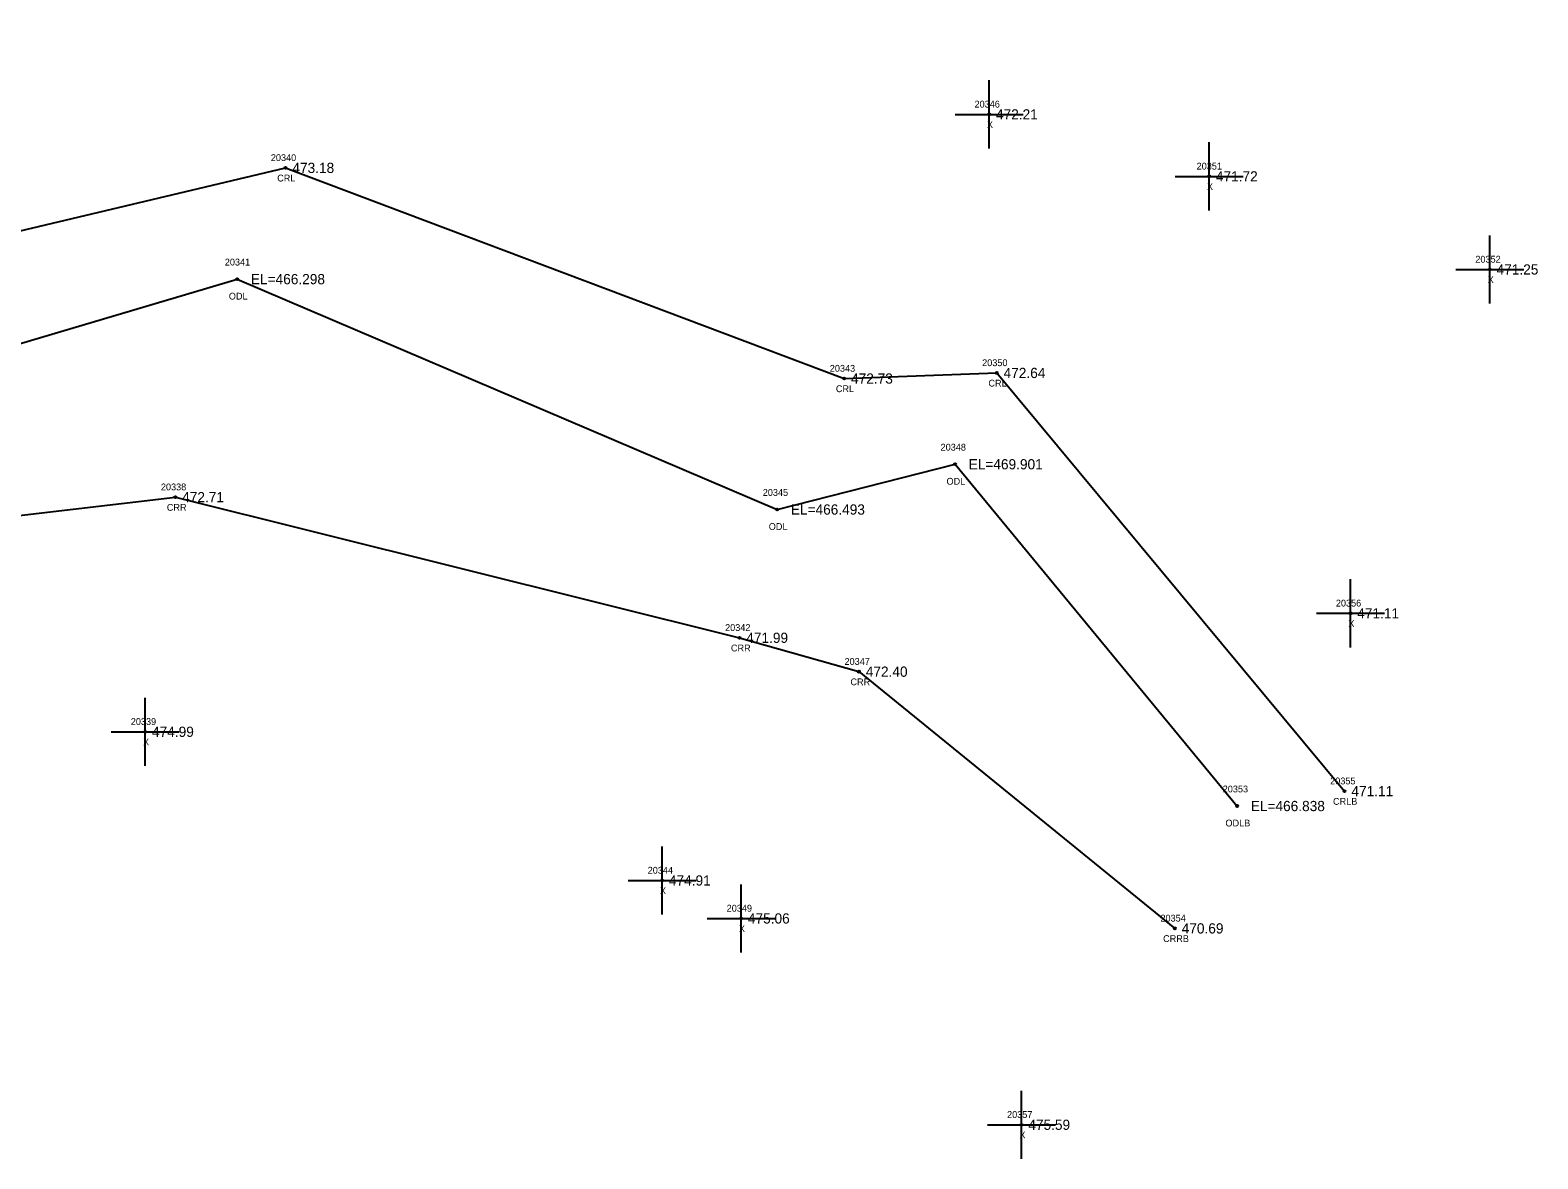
# Model space of a CAD drawing. Extents: x 1789565 to 1790548, y 909019 to 910194.
# Drawn here: x 1790303.1 to 1790524.4, y 909275.5 to 909441.2 of the extents above; entities that cross this region are included whole.
import ezdxf

# ---------------------------------------------------------------- set-up
doc = ezdxf.new("R2010")
doc.units = 0
for name, color, linetype in [('RD_EX_H2O', 7, 'Continuous'), ('RD_EX_H2O_txCode', 7, 'Continuous'), ('RD_EX_Misc', 7, 'Continuous'), ('RD_EX_Misc_txCode', 7, 'Continuous'), ('RD_EX_TX_H2O_ELEV', 7, 'Continuous'), ('RD_EX_TX_Misc_ELEV', 7, 'Continuous'), ('RD_SMD_Locator', 7, 'Continuous')]:
    doc.layers.add(name, color=color, linetype=linetype)

msp = doc.modelspace()

# ---------------------------------------------------------------- linework, layer by layer
at = {"layer": 'RD_EX_H2O'}
for points in [[(1789926.75, 910151.78), (1789921.87, 910061.22), (1789923.33, 910015.8), (1789922.65, 909953.15), (1789957.79, 909859.65), (1789976.3, 909811.78), (1790009.05, 909737.59), (1790033.3, 909656.58), (1790043.84, 909640.77), (1790040.94, 909620.44), (1790068.41, 909598.88), (1790105.46, 909552.21), (1790128.28, 909493.4), (1790125.72, 909445.59), (1790167.31, 909436.17), (1790202.14, 909447.88), (1790216.41, 909437.36), (1790196.97, 909382.86), (1790209.47, 909371.8), (1790248.65, 909379.51), (1790333.47, 909404.65), (1790412.72, 909370.84), (1790438.82, 909377.48), (1790480.23, 909327.32)], [(1789942.19, 910149.47), (1789928.94, 910061.47), (1789937.03, 910016.56), (1789929.09, 909954.8), (1789962.46, 909861.74), (1789984.97, 909814.65), (1790017.82, 909740.15), (1790045.4, 909660.05), (1790055.69, 909646.96), (1790055.38, 909644.82), (1790053.69, 909634.91), (1790054.91, 909627.64), (1790075.55, 909607.72), (1790122.18, 909568.31), (1790142.55, 909490.86), (1790145.56, 909467.27), (1790204.21, 909464.64), (1790228.21, 909444.34), (1790208.83, 909385.44), (1790245.53, 909398.45), (1790340.56, 909420.98), (1790422.56, 909390.06), (1790444.95, 909390.88), (1790496, 909329.5)], [(1790030.97, 909616.21), (1790039.23, 909609.17), (1790060.86, 909590.41), (1790089.09, 909540.87), (1790093.77, 909497), (1790113.81, 909430.51), (1790177.09, 909424.59), (1790197.54, 909430.06), (1790185.17, 909386.39), (1790196.62, 909365.47), (1790247.61, 909363.63), (1790324.38, 909372.65), (1790407.18, 909352.01), (1790424.72, 909347.04), (1790471.09, 909309.36)]]:
    msp.add_lwpolyline(points, dxfattribs=at)
at = {"layer": 'RD_EX_Misc'}
for p, q in [((1790443.83, 909423.83), (1790443.83, 909433.83)), ((1790438.83, 909428.83), (1790448.83, 909428.83)), ((1790476.11, 909414.73), (1790476.11, 909424.73)), ((1790471.11, 909419.73), (1790481.11, 909419.73)), ((1790517.31, 909401.07), (1790517.31, 909411.07)), ((1790512.31, 909406.07), (1790522.31, 909406.07)), ((1790496.86, 909350.6), (1790496.86, 909360.6)), ((1790491.86, 909355.6), (1790501.86, 909355.6)), ((1790319.96, 909333.22), (1790319.96, 909343.22)), ((1790314.96, 909338.22), (1790324.96, 909338.22)), ((1790395.83, 909311.39), (1790395.83, 909321.39)), ((1790390.83, 909316.39), (1790400.83, 909316.39)), ((1790407.42, 909305.82), (1790407.42, 909315.82)), ((1790402.42, 909310.82), (1790412.42, 909310.82)), ((1790448.58, 909275.54), (1790448.58, 909285.54)), ((1790443.58, 909280.54), (1790453.58, 909280.54))]:
    msp.add_line(p, q, dxfattribs=at)
at = {"layer": 'RD_SMD_Locator'}
for centre in [(1790443.83, 909428.83), (1790340.56, 909420.98), (1790476.11, 909419.73), (1790333.47, 909404.65), (1790517.31, 909406.07), (1790444.95, 909390.88), (1790422.56, 909390.06), (1790438.82, 909377.48), (1790324.38, 909372.65), (1790412.72, 909370.84), (1790496.86, 909355.6), (1790407.18, 909352.01), (1790424.72, 909347.04), (1790319.96, 909338.22), (1790496, 909329.5), (1790480.23, 909327.32), (1790395.83, 909316.39), (1790407.42, 909310.82), (1790471.09, 909309.36), (1790448.58, 909280.54)]:
    msp.add_circle(centre, 0.15, dxfattribs=at)

# ---------------------------------------------------------------- texts
at = {"layer": 'RD_EX_H2O_txCode'}
for s, p in [('20340', (1790338.4, 909421.98)), ('CRL', (1790339.33, 909418.98)), ('20341', (1790331.64, 909406.65)), ('ODL', (1790332.23, 909401.65)), ('20343', (1790420.44, 909391.06)), ('20350', (1790442.8, 909391.88)), ('CRL', (1790421.33, 909388.06)), ('CRL', (1790443.72, 909388.88)), ('20348', (1790436.7, 909379.48)), ('ODL', (1790437.57, 909374.48)), ('20338', (1790322.26, 909373.65)), ('20345', (1790410.6, 909372.84)), ('CRR', (1790323.13, 909370.65)), ('ODL', (1790411.48, 909367.84)), ('20342', (1790405.07, 909353.01)), ('CRR', (1790405.93, 909350.01)), ('20347', (1790422.6, 909348.04)), ('CRR', (1790423.47, 909345.04)), ('20355', (1790493.88, 909330.5)), ('20353', (1790478.11, 909329.32)), ('CRLB', (1790494.3, 909327.5)), ('ODLB', (1790478.51, 909324.32)), ('20354', (1790468.97, 909310.36)), ('CRRB', (1790469.36, 909307.36))]:
    msp.add_text(s, height=1, dxfattribs=at).set_placement(p)
at = {"layer": 'RD_EX_Misc_txCode'}
for s, p in [('20346', (1790441.68, 909429.83)), ('X', (1790443.51, 909426.83)), ('20351', (1790474.28, 909420.73)), ('X', (1790475.8, 909417.73)), ('20352', (1790515.19, 909407.07)), ('X', (1790517, 909404.07)), ('20356', (1790494.72, 909356.6)), ('X', (1790496.55, 909353.6)), ('20339', (1790317.84, 909339.22)), ('X', (1790319.64, 909336.22)), ('20344', (1790393.71, 909317.39)), ('X', (1790395.51, 909314.39)), ('20349', (1790405.3, 909311.82)), ('X', (1790407.1, 909308.82)), ('20357', (1790446.46, 909281.54)), ('X', (1790448.27, 909278.54))]:
    msp.add_text(s, height=1, dxfattribs=at).set_placement(p)
at = {"layer": 'RD_EX_TX_H2O_ELEV'}
for s, p in [('473.18', (1790341.56, 909420.23)), ('EL=466.298', (1790335.47, 909403.9)), ('472.64', (1790445.95, 909390.13)), ('472.73', (1790423.56, 909389.31)), ('EL=469.901', (1790440.82, 909376.73)), ('472.71', (1790325.38, 909371.9)), ('EL=466.493', (1790414.72, 909370.09)), ('471.99', (1790408.18, 909351.26)), ('472.40', (1790425.72, 909346.29)), ('471.11', (1790497, 909328.75)), ('EL=466.838', (1790482.23, 909326.57)), ('470.69', (1790472.09, 909308.61))]:
    msp.add_text(s, height=1.5, dxfattribs=at).set_placement(p)
at = {"layer": 'RD_EX_TX_Misc_ELEV'}
for s, p in [('472.21', (1790444.83, 909428.08)), ('471.72', (1790477.11, 909418.98)), ('471.25', (1790518.31, 909405.32)), ('471.11', (1790497.86, 909354.85)), ('474.99', (1790320.96, 909337.47)), ('474.91', (1790396.83, 909315.64)), ('475.06', (1790408.42, 909310.07)), ('475.59', (1790449.58, 909279.79))]:
    msp.add_text(s, height=1.5, dxfattribs=at).set_placement(p)

doc.saveas('drawing.dxf')
